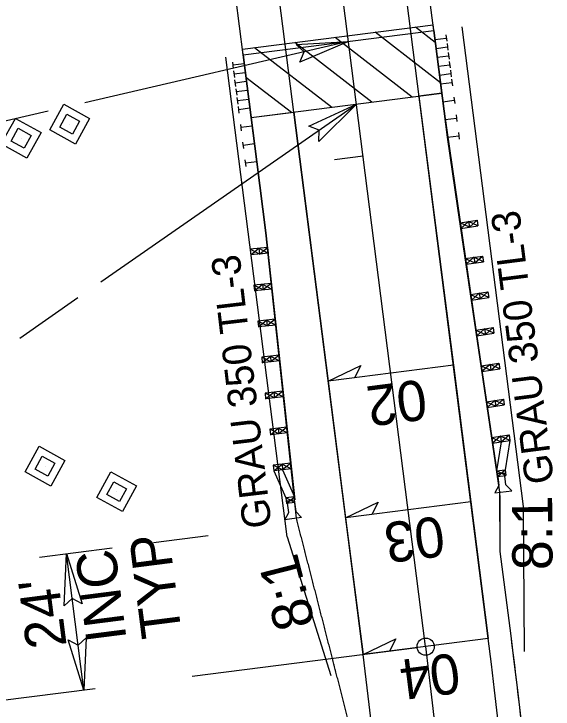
# Model space of a CAD drawing. Extents: x 2167182 to 2168576, y 842635 to 844493.
# Drawn here: x 2168005 to 2168098.9, y 843239.3 to 843360.4 of the extents above; entities that cross this region are included whole.
import ezdxf

# ---------------------------------------------------------------- set-up
doc = ezdxf.new("R2010")
doc.units = 0
for name, color, linetype in [('Prop Approach Slab Hatching', 7, 'Continuous'), ('Prop Conc Curb 8in x 18in - Special', 7, 'Continuous'), ('Prop Dimension', 7, 'Continuous'), ('Prop Dimension Text', 7, 'Continuous'), ('Prop EOT', 7, 'Continuous'), ('Prop Guardrail', 7, 'Continuous'), ('Prop Guardrail Anchor Unit CELL', 7, 'Continuous'), ('Prop Horizontal Alignment', 7, 'Continuous'), ('Prop Horizontal Alignment Station Label', 7, 'Continuous'), ('Prop Horizontal Alignment Tick Small', 7, 'Continuous'), ('Prop Paved Shoulder', 7, 'Continuous'), ('Prop Roadway Bridge', 7, 'Continuous'), ('Prop ROW Marker CELL', 7, 'Continuous'), ('Prop ROW Permanent Easement CELL', 7, 'Continuous'), ('Prop Shade Light', 7, 'Continuous'), ('Prop Structure Anchor Unit CELL', 7, 'Continuous'), ('Prop Superelevation  Arrow CELL', 7, 'Continuous'), ('Prop Superelevation Label', 7, 'Continuous'), ('Prop Terminator CELL', 7, 'Continuous'), ('Scratch_Level_1', 7, 'Continuous'), ('Scratch_Level_6', 7, 'Continuous')]:
    doc.layers.add(name, color=color, linetype=linetype)

# ---------------------------------------------------------------- blocks, each defined once
blk = doc.blocks.new('ROW Marker Permanent Easement-E')
at = {"layer": 'Prop ROW Marker CELL'}
blk.add_line((0, 0), (0, 0), dxfattribs=at)
at = {"layer": 'Prop ROW Permanent Easement CELL'}
for points in [[(0, 0.072), (0.072, 0), (0, -0.072), (-0.072, 0)], [(0, 0.036), (0.036, 0), (0, -0.036), (-0.036, 0)]]:
    blk.add_lwpolyline(points, close=True, dxfattribs=at)

msp = doc.modelspace()

# ---------------------------------------------------------------- linework, layer by layer
at = {"layer": 'Prop Approach Slab Hatching'}
for p, q in [((2168044.79, 843354.24), (2168078.02, 843358.49)), ((2168078.41, 843355.44), (2168074.97, 843358.1)), ((2168079.54, 843346.58), (2168078.02, 843358.49)), ((2168079.31, 843348.42), (2168067.96, 843357.2)), ((2168074.37, 843345.92), (2168060.94, 843356.3)), ((2168060.34, 843344.13), (2168046.92, 843354.51)), ((2168067.35, 843345.03), (2168053.93, 843355.41)), ((2168046.31, 843342.34), (2168044.79, 843354.24)), ((2168053.33, 843343.23), (2168045.42, 843349.35)), ((2168046.31, 843342.34), (2168079.54, 843346.58))]:
    msp.add_line(p, q, dxfattribs=at)
at = {"layer": 'Prop Conc Curb 8in x 18in - Special'}
msp.add_line((2168044.92, 843353.25), (2168047.29, 843334.65), dxfattribs=at)
at = {"layer": 'Prop Dimension'}
for p, q in [((2168029.32, 843268.31), (2168038.85, 843269.53)), ((2168009.46, 843265.77), (2168022.08, 843267.38)), ((2168017.19, 843242.57), (2168014.15, 843266.37))]:
    msp.add_line(p, q, dxfattribs=at)
for points in [[(2168063.27, 843355.59), (2168017.32, 843344.93)], [(2168020.14, 843313.74), (2168064.66, 843344.68)], [(2168010.94, 843343.45), (2167749.88, 843282.86)], [(2168006.02, 843303.93), (2168016.15, 843310.97)]]:
    msp.add_lwpolyline(points, dxfattribs=at)
at = {"layer": 'Prop EOT'}
for p, q in [((2168087.65, 843251.57), (2168041.48, 843612.96)), ((2168065.82, 843248.78), (2168019.66, 843610.17))]:
    msp.add_line(p, q, dxfattribs=at)
for radius in [844, 822]:
    msp.add_arc((2167250.45, 843144.63), radius, 357.48556, 7.27898, dxfattribs=at)
at = {"layer": 'Prop Guardrail'}
for p, q in [((2168080.52, 843338.9), (2168078.15, 843357.49)), ((2168047.29, 843334.65), (2168044.92, 843353.25)), ((2168082.35, 843326.53), (2168080.52, 843338.9)), ((2168047.29, 843334.65), (2168048.88, 843322.25)), ((2168089.68, 843277.06), (2168082.35, 843326.53)), ((2168054.22, 843272.53), (2168048.88, 843322.25))]:
    msp.add_line(p, q, dxfattribs=at)
at = {"layer": 'Prop Guardrail Anchor Unit CELL'}
for p, q in [((2168082.35, 843326.53), (2168089.17, 843280.28)), ((2168082.73, 843324.01), (2168085.69, 843324.45)), ((2168084.21, 843324.23), (2168082.87, 843323.02)), ((2168084.21, 843324.23), (2168084.36, 843323.24)), ((2168085.84, 843323.46), (2168084.21, 843324.23)), ((2168084.36, 843323.24), (2168085.69, 843324.45)), ((2168085.69, 843324.45), (2168085.84, 843323.46)), ((2168082.73, 843324.01), (2168082.87, 843323.02)), ((2168084.36, 843323.24), (2168082.73, 843324.01)), ((2168082.87, 843323.02), (2168085.84, 843323.46)), ((2168082.87, 843323.02), (2168084.36, 843323.24)), ((2168048.88, 843322.25), (2168053.91, 843275.77)), ((2168049.15, 843319.72), (2168046.17, 843319.4)), ((2168047.77, 843318.57), (2168046.17, 843319.4)), ((2168046.17, 843319.4), (2168046.28, 843318.41)), ((2168046.28, 843318.41), (2168047.66, 843319.56)), ((2168047.66, 843319.56), (2168047.77, 843318.57)), ((2168047.66, 843319.56), (2168049.26, 843318.73)), ((2168047.77, 843318.57), (2168049.15, 843319.72)), ((2168049.15, 843319.72), (2168049.26, 843318.73)), ((2168049.26, 843318.73), (2168046.28, 843318.41)), ((2168049.26, 843318.73), (2168047.77, 843318.57)), ((2168083.64, 843317.78), (2168086.66, 843318.22)), ((2168085.3, 843317.01), (2168086.66, 843318.22)), ((2168086.66, 843318.22), (2168086.81, 843317.23)), ((2168083.64, 843317.78), (2168085.3, 843317.01)), ((2168085.15, 843318), (2168083.79, 843316.79)), ((2168083.79, 843316.79), (2168086.81, 843317.23)), ((2168085.15, 843318), (2168085.3, 843317.01)), ((2168086.81, 843317.23), (2168085.15, 843318)), ((2168049.83, 843313.46), (2168046.79, 843313.13)), ((2168046.9, 843312.14), (2168048.31, 843313.29)), ((2168048.31, 843313.29), (2168048.42, 843312.3)), ((2168048.31, 843313.29), (2168049.94, 843312.46)), ((2168049.83, 843313.46), (2168048.42, 843312.3)), ((2168048.42, 843312.3), (2168046.79, 843313.13)), ((2168046.79, 843313.13), (2168046.9, 843312.14)), ((2168049.94, 843312.46), (2168046.9, 843312.14)), ((2168084.56, 843311.54), (2168087.58, 843311.99)), ((2168084.56, 843311.54), (2168086.22, 843310.78)), ((2168086.07, 843311.77), (2168084.71, 843310.55)), ((2168084.71, 843310.55), (2168087.72, 843311)), ((2168086.07, 843311.77), (2168086.22, 843310.78)), ((2168087.72, 843311), (2168086.07, 843311.77)), ((2168086.22, 843310.78), (2168087.58, 843311.99)), ((2168087.58, 843311.99), (2168087.72, 843311)), ((2168050.51, 843307.19), (2168047.48, 843306.87)), ((2168050.51, 843307.19), (2168049.1, 843306.04)), ((2168049.1, 843306.04), (2168047.48, 843306.87)), ((2168047.48, 843306.87), (2168047.58, 843305.87)), ((2168047.58, 843305.87), (2168048.99, 843307.03)), ((2168050.61, 843306.2), (2168047.58, 843305.87)), ((2168048.99, 843307.03), (2168049.1, 843306.04)), ((2168048.99, 843307.03), (2168050.61, 843306.2)), ((2168085.48, 843305.31), (2168088.48, 843305.75)), ((2168085.48, 843305.31), (2168085.63, 843304.32)), ((2168085.48, 843305.31), (2168087.13, 843304.54)), ((2168086.98, 843305.53), (2168085.63, 843304.32)), ((2168085.63, 843304.32), (2168088.63, 843304.76)), ((2168086.98, 843305.53), (2168087.13, 843304.54)), ((2168088.63, 843304.76), (2168086.98, 843305.53)), ((2168087.13, 843304.54), (2168088.48, 843305.75)), ((2168088.48, 843305.75), (2168088.63, 843304.76)), ((2168051.18, 843300.93), (2168048.17, 843300.6)), ((2168049.78, 843299.77), (2168048.17, 843300.6)), ((2168048.17, 843300.6), (2168048.27, 843299.61)), ((2168048.27, 843299.61), (2168049.68, 843300.77)), ((2168051.29, 843299.94), (2168048.27, 843299.61)), ((2168049.68, 843300.77), (2168049.78, 843299.77)), ((2168049.68, 843300.77), (2168051.29, 843299.94)), ((2168051.18, 843300.93), (2168049.78, 843299.77)), ((2168051.18, 843300.93), (2168051.29, 843299.94)), ((2168086.4, 843299.08), (2168089.5, 843299.53)), ((2168086.4, 843299.08), (2168088.1, 843298.32)), ((2168087.95, 843299.31), (2168086.54, 843298.09)), ((2168087.95, 843299.31), (2168088.1, 843298.32)), ((2168089.65, 843298.54), (2168087.95, 843299.31)), ((2168088.1, 843298.32), (2168089.5, 843299.53)), ((2168089.5, 843299.53), (2168089.65, 843298.54)), ((2168086.54, 843298.09), (2168089.65, 843298.54)), ((2168051.86, 843294.67), (2168048.74, 843294.33)), ((2168050.41, 843293.5), (2168048.74, 843294.33)), ((2168048.74, 843294.33), (2168048.85, 843293.33)), ((2168048.85, 843293.33), (2168050.3, 843294.5)), ((2168050.3, 843294.5), (2168050.41, 843293.5)), ((2168050.3, 843294.5), (2168051.97, 843293.67)), ((2168051.86, 843294.67), (2168050.41, 843293.5)), ((2168051.97, 843293.67), (2168048.85, 843293.33)), ((2168087.32, 843292.84), (2168090.28, 843293.28)), ((2168087.32, 843292.84), (2168088.95, 843292.07)), ((2168088.8, 843293.06), (2168087.46, 843291.85)), ((2168088.8, 843293.06), (2168088.95, 843292.07)), ((2168090.43, 843292.29), (2168088.8, 843293.06)), ((2168088.95, 843292.07), (2168090.28, 843293.28)), ((2168090.28, 843293.28), (2168090.43, 843292.29)), ((2168087.46, 843291.85), (2168090.43, 843292.29)), ((2168052.54, 843288.4), (2168049.56, 843288.08)), ((2168051.16, 843287.24), (2168049.56, 843288.08)), ((2168049.56, 843288.08), (2168049.67, 843287.08)), ((2168049.67, 843287.08), (2168051.05, 843288.24)), ((2168051.05, 843288.24), (2168051.16, 843287.24)), ((2168051.05, 843288.24), (2168052.65, 843287.41)), ((2168052.54, 843288.4), (2168051.16, 843287.24)), ((2168052.65, 843287.41), (2168049.67, 843287.08)), ((2168088.23, 843286.61), (2168091.27, 843287.05)), ((2168088.23, 843286.61), (2168089.9, 843285.84)), ((2168089.75, 843286.83), (2168088.38, 843285.62)), ((2168089.75, 843286.83), (2168089.9, 843285.84)), ((2168091.41, 843286.07), (2168089.75, 843286.83)), ((2168089.9, 843285.84), (2168091.27, 843287.05)), ((2168091.27, 843287.05), (2168091.41, 843286.07)), ((2168088.38, 843285.62), (2168091.41, 843286.07)), ((2168089.9, 843285.84), (2168089.09, 843280.77)), ((2168091.41, 843286.07), (2168090.58, 843280.99)), ((2168053.22, 843282.14), (2168050.17, 843281.81)), ((2168051.8, 843280.98), (2168050.17, 843281.81)), ((2168050.17, 843281.81), (2168050.28, 843280.81)), ((2168050.28, 843280.81), (2168051.7, 843281.97)), ((2168051.7, 843281.97), (2168051.8, 843280.98)), ((2168051.7, 843281.97), (2168053.33, 843281.14)), ((2168053.22, 843282.14), (2168051.8, 843280.98)), ((2168053.33, 843281.14), (2168050.28, 843280.81)), ((2168050.28, 843280.81), (2168052.36, 843276.11)), ((2168051.8, 843280.98), (2168053.85, 843276.27)), ((2168089.09, 843280.77), (2168090.58, 843280.99)), ((2168090.73, 843280), (2168089.09, 843280.77)), ((2168089.24, 843279.78), (2168090.58, 843280.99)), ((2168090.58, 843280.99), (2168090.65, 843280.49)), ((2168090.58, 843280.99), (2168090.73, 843280)), ((2168089.24, 843279.78), (2168090.73, 843280)), ((2168089.85, 843280.33), (2168089.25, 843280.25)), ((2168089.25, 843280.25), (2168089.51, 843278.22)), ((2168090.46, 843280.41), (2168089.85, 843280.33)), ((2168090.72, 843278.38), (2168090.46, 843280.41)), ((2168089.51, 843278.22), (2168088.8, 843276.95)), ((2168091.72, 843277.32), (2168090.72, 843278.38)), ((2168088.8, 843276.95), (2168091.72, 843277.32)), ((2168053.85, 843276.27), (2168052.36, 843276.11)), ((2168052.36, 843276.11), (2168052.42, 843275.61)), ((2168053.96, 843275.27), (2168052.36, 843276.11)), ((2168052.36, 843276.11), (2168052.47, 843275.11)), ((2168052.47, 843275.11), (2168053.85, 843276.27)), ((2168053.23, 843275.66), (2168053.84, 843275.73)), ((2168053.84, 843275.73), (2168054.09, 843273.7)), ((2168053.96, 843275.27), (2168052.47, 843275.11)), ((2168052.62, 843275.58), (2168053.23, 843275.66)), ((2168052.88, 843273.55), (2168052.62, 843275.58)), ((2168052.18, 843272.27), (2168052.88, 843273.55)), ((2168054.09, 843273.7), (2168055.1, 843272.64)), ((2168055.1, 843272.64), (2168052.18, 843272.27))]:
    msp.add_line(p, q, dxfattribs=at)
at = {"layer": 'Prop Horizontal Alignment'}
msp.add_line((2168076.73, 843250.17), (2168030.57, 843611.57), dxfattribs=at)
msp.add_arc((2167250.45, 843144.63), 833, 357.48556, 7.27898, dxfattribs=at)
at = {"layer": 'Prop Horizontal Alignment Station Label'}
for p, q in [((2168075.25, 843249.98), (2168036.03, 843244.97)), ((2168019.14, 843242.82), (2167960.63, 843235.34))]:
    msp.add_line(p, q, dxfattribs=at)
msp.add_circle((2168076.73, 843250.17), 1.5, dxfattribs=at)
at = {"layer": 'Prop Horizontal Alignment Tick Small'}
msp.add_line((2168065.82, 843335.61), (2168060.86, 843334.97), dxfattribs=at)
at = {"layer": 'Prop Paved Shoulder'}
msp.add_line((2168091.61, 843252.07), (2168089.74, 843266.74), dxfattribs=at)
msp.add_arc((2167250.45, 843144.63), 848, 3.55368, 7.27898, dxfattribs=at)
for points in [[(2168089.74, 843266.74), (2168089.74, 843266.88), (2168089.74, 843267.02), (2168089.74, 843267.16), (2168089.74, 843267.3), (2168089.74, 843267.44), (2168089.73, 843267.58), (2168089.73, 843267.72), (2168089.73, 843267.86), (2168089.73, 843268), (2168089.73, 843268.14), (2168089.73, 843268.27), (2168089.73, 843268.41), (2168089.73, 843268.55), (2168089.73, 843268.69), (2168089.73, 843268.83), (2168089.73, 843268.97), (2168089.73, 843269.11), (2168089.73, 843269.25), (2168089.72, 843269.39), (2168089.72, 843269.53), (2168089.72, 843269.67), (2168089.72, 843269.81), (2168089.72, 843269.95), (2168089.72, 843270.09), (2168089.72, 843270.23), (2168089.72, 843270.37), (2168089.72, 843270.51), (2168089.72, 843270.64), (2168089.72, 843270.78), (2168089.72, 843270.92), (2168089.72, 843271.06), (2168089.71, 843271.2), (2168089.71, 843271.34), (2168089.71, 843271.48), (2168089.71, 843271.62), (2168089.71, 843271.76), (2168089.71, 843271.9), (2168089.71, 843272.04), (2168089.71, 843272.18), (2168089.71, 843272.32), (2168089.71, 843272.46), (2168089.71, 843272.6), (2168089.71, 843272.74), (2168089.71, 843272.87), (2168089.7, 843273.01), (2168089.7, 843273.15), (2168089.7, 843273.29), (2168089.7, 843273.43), (2168089.7, 843273.57), (2168089.7, 843273.71), (2168089.7, 843273.85), (2168089.7, 843273.99), (2168089.7, 843274.13), (2168089.7, 843274.27), (2168089.7, 843274.41), (2168089.7, 843274.55), (2168089.69, 843274.69), (2168089.69, 843274.83), (2168089.69, 843274.97), (2168089.69, 843275.11), (2168089.69, 843275.24), (2168089.69, 843275.38), (2168089.69, 843275.52), (2168089.69, 843275.66), (2168089.69, 843275.8), (2168089.69, 843275.94), (2168089.69, 843276.08), (2168089.69, 843276.22), (2168089.69, 843276.36), (2168089.68, 843276.5), (2168089.68, 843276.64), (2168089.68, 843276.78), (2168089.68, 843277.06)], [(2168063.15, 843237.58), (2168063.03, 843238.04), (2168062.92, 843238.51), (2168062.8, 843238.98), (2168062.69, 843239.45), (2168062.57, 843239.91), (2168062.46, 843240.38), (2168062.34, 843240.85), (2168062.22, 843241.31), (2168062.11, 843241.78), (2168061.99, 843242.25), (2168061.87, 843242.71), (2168061.75, 843243.18), (2168061.64, 843243.65), (2168061.52, 843244.11), (2168061.4, 843244.58), (2168061.28, 843245.05), (2168061.16, 843245.51), (2168061.04, 843245.98), (2168060.92, 843246.44), (2168060.8, 843246.91), (2168060.68, 843247.37), (2168060.56, 843247.84), (2168060.44, 843248.31), (2168060.32, 843248.78), (2168060.2, 843249.26), (2168060.07, 843249.73), (2168059.95, 843250.21), (2168059.83, 843250.68), (2168059.71, 843251.16), (2168059.59, 843251.63), (2168059.46, 843252.11), (2168059.34, 843252.58), (2168059.22, 843253.06), (2168059.1, 843253.53), (2168058.98, 843254.01), (2168058.85, 843254.48), (2168058.73, 843254.96), (2168058.61, 843255.43), (2168058.49, 843255.91), (2168058.37, 843256.38), (2168058.24, 843256.86), (2168058.12, 843257.33), (2168058, 843257.81), (2168057.88, 843258.28), (2168057.76, 843258.76), (2168057.63, 843259.23), (2168057.51, 843259.71), (2168057.39, 843260.18), (2168057.27, 843260.66), (2168057.15, 843261.13), (2168057.02, 843261.61), (2168056.9, 843262.08), (2168056.78, 843262.56), (2168056.66, 843263.03), (2168056.54, 843263.51), (2168056.42, 843263.98), (2168056.29, 843264.45), (2168056.17, 843264.93), (2168056.05, 843265.4), (2168055.93, 843265.88), (2168055.81, 843266.35), (2168055.68, 843266.83), (2168055.56, 843267.3), (2168055.44, 843267.78), (2168055.32, 843268.25), (2168055.2, 843268.73), (2168055.07, 843269.2), (2168054.95, 843269.68), (2168054.83, 843270.15), (2168054.71, 843270.63), (2168054.59, 843271.1), (2168054.46, 843271.58), (2168054.22, 843272.53)]]:
    msp.add_spline(points, degree=3, dxfattribs=at)
at = {"layer": 'Prop Roadway Bridge'}
for p, q in [((2168078.15, 843357.49), (2168061.36, 843488.93)), ((2168044.92, 843353.25), (2168028.13, 843484.68)), ((2168044.92, 843353.25), (2168078.15, 843357.49))]:
    msp.add_line(p, q, dxfattribs=at)
at = {"layer": 'Prop Shade Light'}
for p, q in [((2168079.54, 843346.58), (2168075.57, 843346.08)), ((2168075.57, 843346.08), (2168075.57, 843346.08)), ((2168075.57, 843346.08), (2168075.57, 843346.08)), ((2168075.57, 843346.08), (2168075.57, 843346.08)), ((2168079.54, 843346.58), (2168079.54, 843346.58)), ((2168079.54, 843346.58), (2168079.54, 843346.58)), ((2168046.31, 843342.34), (2168053.75, 843343.29)), ((2168047.29, 843334.65), (2168046.31, 843342.34)), ((2168053.75, 843343.29), (2168053.75, 843343.29)), ((2168048.88, 843322.25), (2168047.29, 843334.65)), ((2168054.22, 843272.53), (2168048.88, 843322.25))]:
    msp.add_line(p, q, dxfattribs=at)
for points in [[(2168075.57, 843346.08), (2168081.56, 843299.18), (2168084.6, 843275.37), (2168087.65, 843251.57)], [(2168079.55, 843346.53), (2168079.54, 843346.58), (2168079.54, 843346.58)], [(2168091.61, 843252.07), (2168089.74, 843266.74), (2168089.68, 843277.06), (2168079.55, 843346.53)], [(2168053.75, 843343.29), (2168059.74, 843296.39), (2168062.78, 843272.58), (2168065.82, 843248.78)]]:
    msp.add_lwpolyline(points, dxfattribs=at)
for radius in [844, 848, 822]:
    msp.add_arc((2167250.45, 843144.63), radius, 357.48556, 7.27898, dxfattribs=at)
msp.add_spline([(2168063.15, 843237.58), (2168063.03, 843238.04), (2168062.92, 843238.51), (2168062.8, 843238.98), (2168062.69, 843239.45), (2168062.57, 843239.91), (2168062.46, 843240.38), (2168062.34, 843240.85), (2168062.22, 843241.31), (2168062.11, 843241.78), (2168061.99, 843242.25), (2168061.87, 843242.71), (2168061.75, 843243.18), (2168061.64, 843243.65), (2168061.52, 843244.11), (2168061.4, 843244.58), (2168061.28, 843245.05), (2168061.16, 843245.51), (2168061.04, 843245.98), (2168060.92, 843246.44), (2168060.8, 843246.91), (2168060.68, 843247.37), (2168060.56, 843247.84), (2168060.44, 843248.31), (2168060.32, 843248.78), (2168060.2, 843249.26), (2168060.07, 843249.73), (2168059.95, 843250.21), (2168059.83, 843250.68), (2168059.71, 843251.16), (2168059.59, 843251.63), (2168059.46, 843252.11), (2168059.34, 843252.58), (2168059.22, 843253.06), (2168059.1, 843253.53), (2168058.98, 843254.01), (2168058.85, 843254.48), (2168058.73, 843254.96), (2168058.61, 843255.43), (2168058.49, 843255.91), (2168058.37, 843256.38), (2168058.24, 843256.86), (2168058.12, 843257.33), (2168058, 843257.81), (2168057.88, 843258.28), (2168057.76, 843258.76), (2168057.63, 843259.23), (2168057.51, 843259.71), (2168057.39, 843260.18), (2168057.27, 843260.66), (2168057.15, 843261.13), (2168057.02, 843261.61), (2168056.9, 843262.08), (2168056.78, 843262.56), (2168056.66, 843263.03), (2168056.54, 843263.51), (2168056.42, 843263.98), (2168056.29, 843264.45), (2168056.17, 843264.93), (2168056.05, 843265.4), (2168055.93, 843265.88), (2168055.81, 843266.35), (2168055.68, 843266.83), (2168055.56, 843267.3), (2168055.44, 843267.78), (2168055.32, 843268.25), (2168055.2, 843268.73), (2168055.07, 843269.2), (2168054.95, 843269.68), (2168054.83, 843270.15), (2168054.71, 843270.63), (2168054.59, 843271.1), (2168054.46, 843271.58), (2168054.22, 843272.53)], degree=3, dxfattribs=at)
at = {"layer": 'Prop Structure Anchor Unit CELL'}
for p, q in [((2168078.15, 843357.49), (2168080.52, 843338.9)), ((2168078.35, 843355.94), (2168080.33, 843356.2)), ((2168080.26, 843356.77), (2168080.4, 843355.63)), ((2168078.54, 843354.39), (2168080.53, 843354.65)), ((2168080.45, 843355.22), (2168080.6, 843354.08)), ((2168044.92, 843353.25), (2168047.29, 843334.65)), ((2168080.65, 843353.67), (2168080.8, 843352.53)), ((2168043.06, 843352.01), (2168043.2, 843350.88)), ((2168078.74, 843352.84), (2168080.73, 843353.1)), ((2168080.85, 843352.12), (2168081, 843350.98)), ((2168045.12, 843351.7), (2168043.13, 843351.45)), ((2168078.94, 843351.29), (2168080.92, 843351.55)), ((2168043.26, 843350.46), (2168043.4, 843349.33)), ((2168045.31, 843350.15), (2168043.33, 843349.9)), ((2168079.14, 843349.74), (2168081.12, 843350)), ((2168081.05, 843350.57), (2168081.19, 843349.43)), ((2168043.45, 843348.91), (2168043.6, 843347.78)), ((2168045.51, 843348.6), (2168043.53, 843348.35)), ((2168079.34, 843348.19), (2168081.32, 843348.45)), ((2168081.25, 843349.02), (2168081.39, 843347.88)), ((2168043.65, 843347.36), (2168043.8, 843346.23)), ((2168045.71, 843347.05), (2168043.73, 843346.8)), ((2168043.85, 843345.81), (2168044, 843344.68)), ((2168045.91, 843345.5), (2168043.92, 843345.25)), ((2168079.73, 843345.09), (2168081.71, 843345.35)), ((2168081.64, 843345.92), (2168081.79, 843344.78)), ((2168044.05, 843344.26), (2168044.19, 843343.13)), ((2168046.11, 843343.95), (2168044.12, 843343.7)), ((2168082.04, 843342.82), (2168082.18, 843341.68)), ((2168044.44, 843341.16), (2168044.59, 843340.03)), ((2168080.13, 843341.99), (2168082.11, 843342.25)), ((2168046.5, 843340.85), (2168044.52, 843340.6)), ((2168080.52, 843338.9), (2168082.51, 843339.15)), ((2168082.43, 843339.72), (2168082.58, 843338.58)), ((2168044.84, 843338.07), (2168044.99, 843336.93)), ((2168046.9, 843337.75), (2168044.91, 843337.5)), ((2168045.24, 843334.97), (2168045.38, 843333.83)), ((2168047.29, 843334.65), (2168045.31, 843334.4))]:
    msp.add_line(p, q, dxfattribs=at)
at = {"layer": 'Prop Superelevation  Arrow CELL'}
for p, q in [((2168081.56, 843299.18), (2168059.74, 843296.39)), ((2168084.6, 843275.37), (2168062.78, 843272.58)), ((2168087.65, 843251.57), (2168065.82, 843248.78))]:
    msp.add_line(p, q, dxfattribs=at)
for points in [[(2168059.74, 843296.39), (2168065.44, 843299.13), (2168064.33, 843296.98)], [(2168062.78, 843272.58), (2168068.48, 843275.33), (2168067.37, 843273.17)], [(2168065.82, 843248.78), (2168071.52, 843251.52), (2168070.41, 843249.36)]]:
    msp.add_lwpolyline(points, close=True, dxfattribs=at)
at = {"layer": 'Prop Terminator CELL'}
for points in [[(2168054.15, 843355.07), (2168063.27, 843355.59), (2168054.81, 843351.99), (2168055.57, 843353.81)], [(2168056.39, 843340.82), (2168064.66, 843344.68), (2168058.14, 843338.2), (2168058.17, 843340.17)], [(2168013.75, 843257.25), (2168014.15, 843266.37), (2168016.88, 843257.6), (2168015.15, 843258.53)], [(2168017.59, 843251.69), (2168017.19, 843242.57), (2168014.46, 843251.34), (2168016.19, 843250.4)]]:
    msp.add_lwpolyline(points, close=True, dxfattribs=at)
at = {"layer": 'Scratch_Level_1'}
for p, q in [((2168093.78, 843274.56), (2168083.11, 843358.13)), ((2168052.62, 843269.3), (2168041.94, 843352.87)), ((2168093.98, 843249.32), (2168093.78, 843274.56)), ((2168052.62, 843269.3), (2168060.23, 843245.13))]:
    msp.add_line(p, q, dxfattribs=at)
at = {"layer": 'Scratch_Level_6'}
for p, q in [((2168089.68, 843277.06), (2168082.35, 843326.53)), ((2168054.22, 843272.53), (2168048.88, 843322.25))]:
    msp.add_line(p, q, dxfattribs=at)

# ---------------------------------------------------------------- block references
at = {"layer": 'Prop Dimension', "xscale": 50.00000000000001, "yscale": 50, "rotation": 106.1236352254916}
for p in [(2168014.71, 843341.19), (2168006.25, 843338.74), (2168010.41, 843281.61), (2168022.9, 843277.17)]:
    msp.add_blockref('ROW Marker Permanent Easement-E', p, dxfattribs=at)

# ---------------------------------------------------------------- texts
at = {"layer": 'Prop Dimension Text'}
for s, rotation, p in [('8:1', 90.3193, (2168098.84, 843263.5)), ('TYP', 97.279, (2168034.26, 843252.14)), ('INC', 97.279, (2168024.63, 843251.45)), ('8:1', 104.3311, (2168057.48, 843254.1)), ("24'", 97.279, (2168014.19, 843250.31))]:
    msp.add_text(s, height=7, rotation=rotation, dxfattribs=at).set_placement(p)
at = {"layer": 'Prop Guardrail Anchor Unit CELL'}
for rotation, p in [(97.279, (2168099.11, 843278.83)), (96.7338, (2168049.91, 843271.08))]:
    msp.add_text('GRAU 350 TL-3', height=5, rotation=rotation, dxfattribs=at).set_placement(p)
at = {"layer": 'Prop Superelevation Label'}
for s, p in [('02', (2168076.42, 843296.76)), ('03', (2168079.52, 843272.96)), ('04', (2168082.2, 843249.11))]:
    msp.add_text(s, height=7, rotation=187.279, dxfattribs=at).set_placement(p)

doc.saveas('drawing.dxf')
